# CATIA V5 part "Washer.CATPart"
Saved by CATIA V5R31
Part number: washer
Bounding box of the stored display mesh (mm): x -24 to 24, y -23.825 to 23.825, z 0 to 3
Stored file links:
  D:\PROJECTS\Project 2021\US EDITION\CATIA V5 6R 2021\Resources\Part Files\c14_catia_v5_6r2021_prt\c14-catia-v5-6r2021-figr-14-26 & 27\Part & Asm\Washer.CATPart
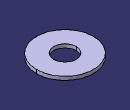
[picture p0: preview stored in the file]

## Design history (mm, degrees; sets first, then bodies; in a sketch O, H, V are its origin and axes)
Body1 (main body)
  Sketch1 on xy-plane, origin (0, 0, 0), H (1, 0, 0), V (0, 1, 0)
    circle A1 centre (0, 0) radius 24
    circle A2 centre (0, 0) radius 9.5
    radius A1 = 24
    radius A2 = 9.5
  Pad1: profile Sketch1, direction (0, 0, 1), length 3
